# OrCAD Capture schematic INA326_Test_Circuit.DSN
size A; title: INA326, Precision, Rail-to-Rail I/O INSTRUMENTATION AMPLIFIER; rev: 1.1; note: Datasheet: SBOS222D EVM: NA; note: Reference
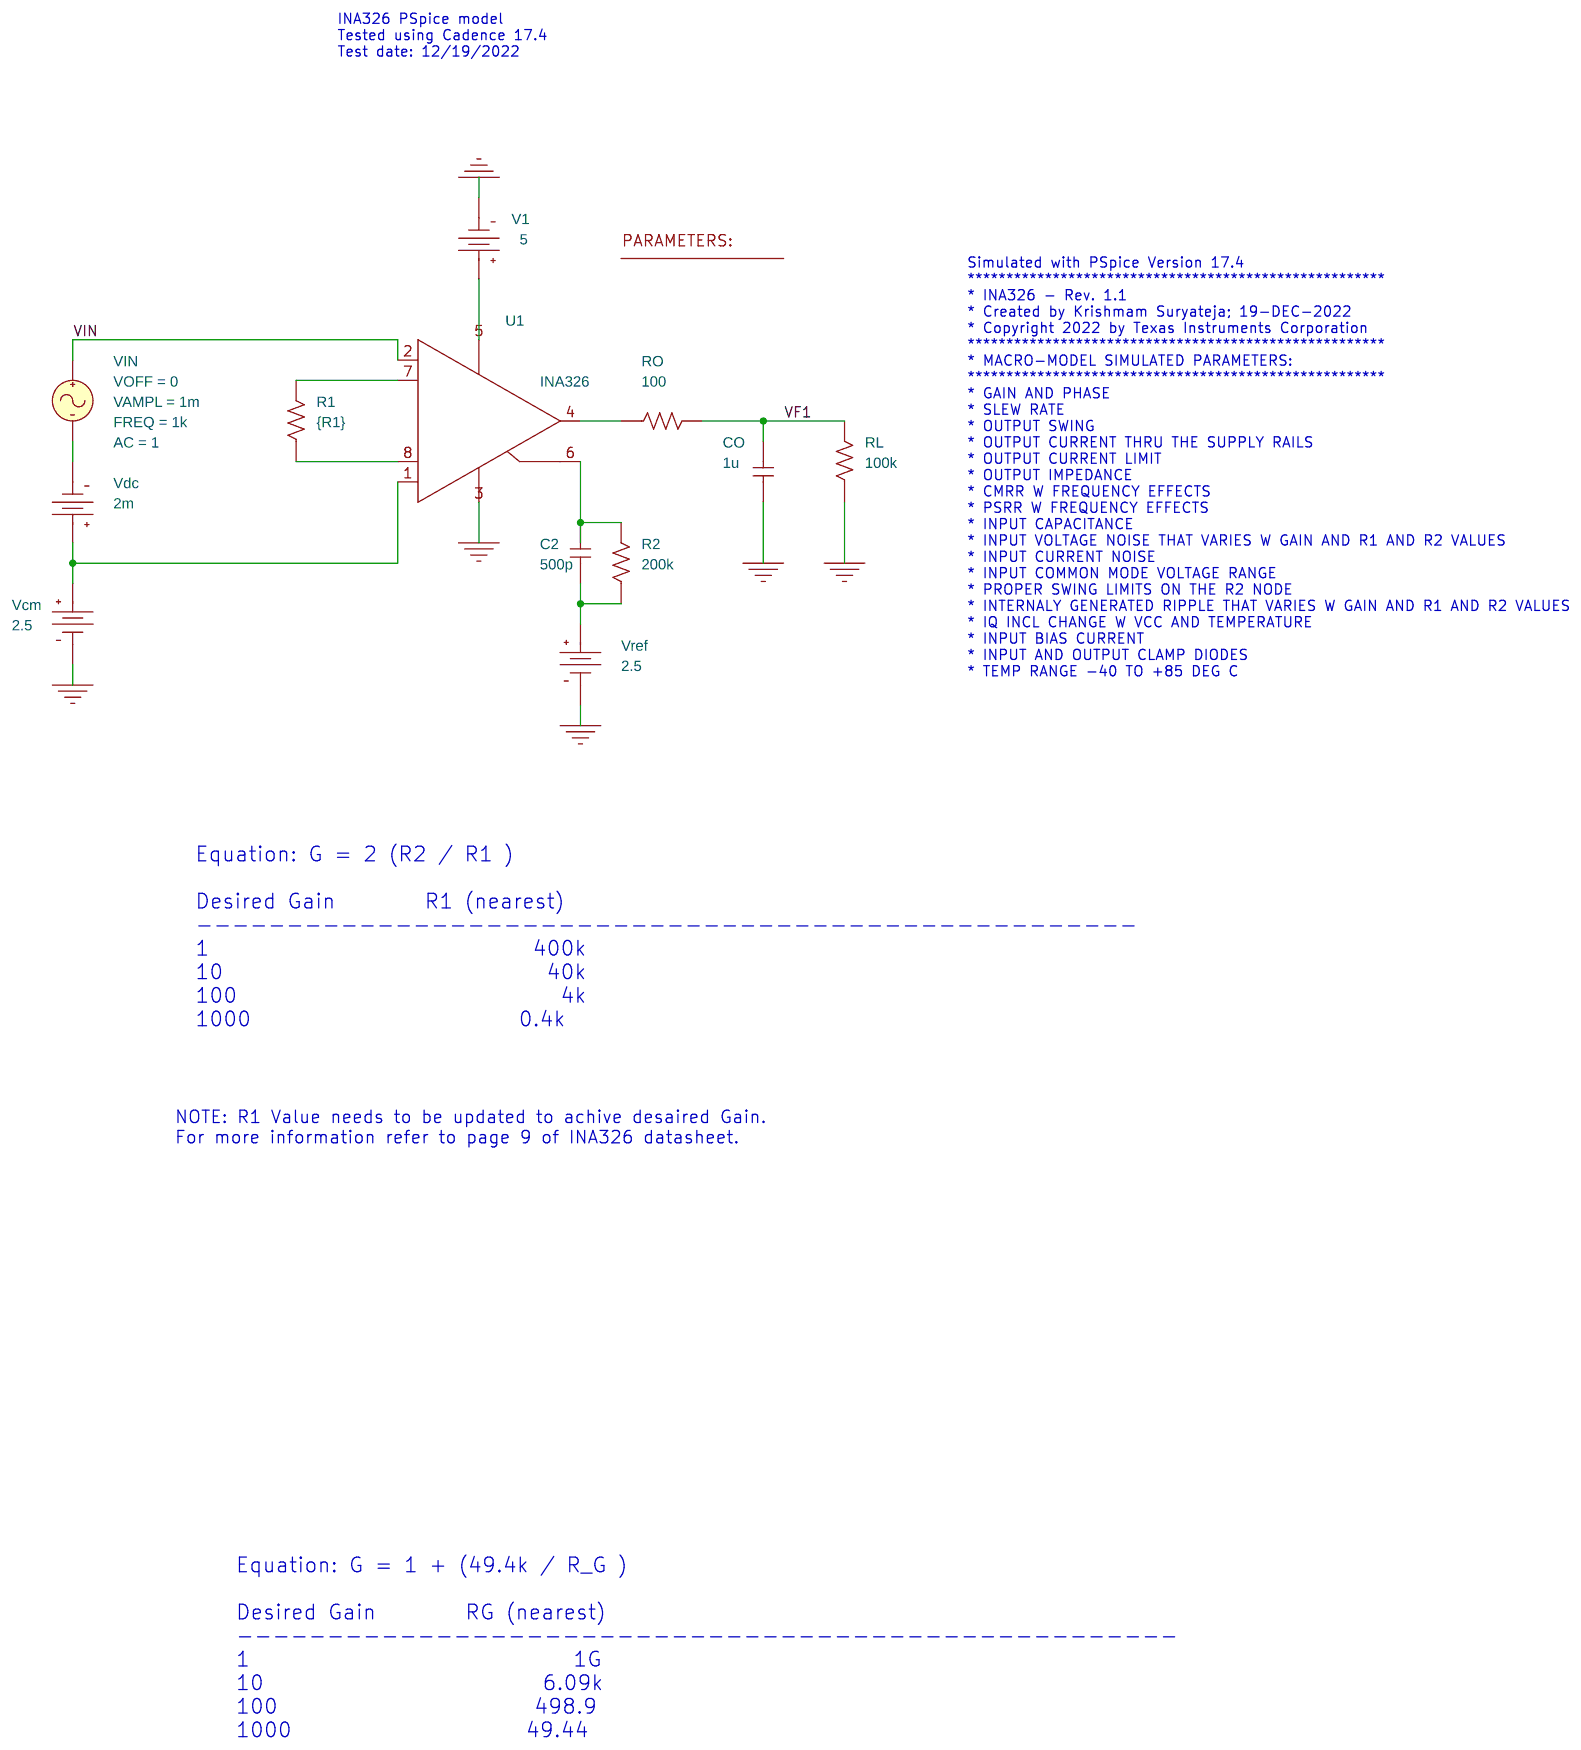
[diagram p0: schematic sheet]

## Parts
1  PARAM
C2  500p  [RAD/CK05]
CO  1u  [RAD/CK05]
R1  {R1}  [AX/RC05]
R2  200k  [AX/RC05]
RL  100k  [AX/RC05]
RO  100  [AX/RC05]
U1  INA326
V1  VDC
Vcm  VDC
Vdc  VDC
VIN  VSIN
Vref  VDC

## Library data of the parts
1 = PARAM: R1: 4k
C2 CO = C
R1 R2 RL RO = R
U1 = INA326
V1 = VDC: DC: 5
Vcm Vref = VDC: DC: 2.5
Vdc = VDC: DC: 2m
VIN = VSIN: AC: 1; FREQ: 1k; VAMPL: 1m; VOFF: 0

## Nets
VIN: U1.2(-) VIN.1(+)
0: CO.1 RL.1 U1.3(V-) V1.1(-) Vcm.1(-) Vref.1(-)
VF1: CO.2 RL.2 RO.2
N14289386: U1.1(+) Vcm.0(+) Vdc.0(+)
N14289409: Vdc.1(-) VIN.2(-)
N14289716: R1.2 U1.7(R1_1)
N14290510: C2.2 R2.2 U1.6(R2)
N14290576: C2.1 R2.1 Vref.0(+)
N14290922: RO.1 U1.4(OUT)
N14296222: R1.1 U1.8(R1_2)
N14296464: U1.5(V+) V1.0(+)

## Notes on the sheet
- INA326 PSpice model
  Tested using Cadence 17.4
  Test date: 12/19/2022
- Simulated with PSpice Version 17.4
  ******************************************************
  * INA326 - Rev. 1.1
  * Created by Krishmam Suryateja; 19-DEC-2022
  * Copyright 2022 by Texas Instruments Corporation
  ******************************************************
  * MACRO-MODEL SIMULATED PARAMETERS:
  ******************************************************
  * GAIN AND PHASE
  * SLEW RATE
  * OUTPUT SWING
  * OUTPUT CURRENT THRU THE SUPPLY RAILS
  * OUTPUT CURRENT LIMIT
  * OUTPUT IMPEDANCE
  * CMRR W FREQUENCY EFFECTS
  * PSRR W FREQUENCY EFFECTS
  * INPUT CAPACITANCE
  * INPUT VOLTAGE NOISE THAT VARIES W GAIN AND R1 AND R2 VALUES
  * INPUT CURRENT NOISE
  * INPUT COMMON MODE VOLTAGE RANGE
  * PROPER SWING LIMITS ON THE R2 NODE
  * INTERNALY GENERATED RIPPLE THAT VARIES W GAIN AND R1 AND R2 VALUES
  * IQ INCL CHANGE W VCC AND TEMPERATURE
  * INPUT BIAS CURRENT
  * INPUT AND OUTPUT CLAMP DIODES
  * TEMP RANGE -40 TO +85 DEG C
- Equation: G = 2 (R2 / R1 )
  Desired Gain        R1 (nearest)
  ----------------------------------------------------
  1                             400k
  10                             40k
  100                             4k
  1000                        0.4k
- NOTE: R1 Value needs to be updated to achive desaired Gain.
- For more information refer to page 9 of INA326 datasheet.
- Equation: G = 1 + (49.4k / R_G )
  Desired Gain        RG (nearest)
  ----------------------------------------------------
  1                             1G
  10                         6.09k
  100                       498.9
  1000                     49.44
